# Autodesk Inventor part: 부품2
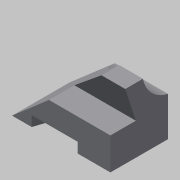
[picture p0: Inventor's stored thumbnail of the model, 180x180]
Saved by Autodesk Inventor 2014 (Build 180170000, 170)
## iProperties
Created: 2015-04
Part Number: 부품2
Material: Generic
Document SubType Name: Modeling
Designer: 203-09
Density: 1 g/cm^3
Appearance: Default
Author: 203-09
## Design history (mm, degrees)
sketch "스케치2"
  geometry: L1 (-43.267, -8)-(-67.621, -8); L2 (-67.621, -8)-(-53, -53); L3 (-53, -53)-(-88, -53); L4 (-88, -53)-(-88, -97); L5 (-88, -97)-(-9, -97); L6 (-9, -97)-(-9, -43.07); A1 r 44 centre (0, 0) between (-43.267, -8) and (-9, -43.07); 1 further point
  constraints: 12 end point, 3 parallel, 2 point on circle, 1 centre point, 1 coincident, 1 horizontal, 1 perpendicular
  dimensions: "d0" = 44 radius of A1; "d1" = 8 distance from line of point (0, 0) L1; "d2" = 9 distance from line of point (0, 0) L6; "d3" = 72 deg angle of L3 L2; "d4" = 44 distance of L3.end L4.end; "d5" = 79 distance of L4.end L5.end; "d6" = 89 distance between parallel lines of L1 L5; "d7" = 35 distance of L2.end L3.end
extrude "돌출1" new body sketch "스케치2" distance "d8" = 135; taper "d9" = 0 deg
sketch "스케치3"
  geometry: L1 (0, -97)-(0, -53) reference; L2 (0, -8)-(-135, -8) reference; L3 (0, -97)-(-102.383, -8); L4 (0, -8)-(0, -97); L5 (0, -8)-(-102.383, -8); L6 (0, -97)-(-135, -97) reference; 1 further point
  constraints: 6 end point, 1 collinear, 1 perpendicular, 1 point on line
  dimensions: "d10" = 139 deg angle of L3 L6
extrude "돌출2" cut sketch "스케치3" stored distance "d11" = 135; taper "d12" = 0 deg
sketch "스케치4"
  geometry: L1 (135, 79)-(0, 79) reference; L2 (135, 0)-(0, 0) reference; L3 (82.331, 79)-(108, 0); L4 (19.244, 79)-(44.912, 0); L5 (82.331, 79)-(19.244, 79); L6 (108, 0)-(44.912, 0); 1 further point
  constraints: 8 end point, 4 point on line, 2 collinear, 1 parallel
  dimensions: "d13" = 27 distance of L3.end L2.start; "d15" = 72 deg angle of L3 L1; "d16" = 60 distance between parallel lines of L4 L3
extrude "돌출3" cut sketch "스케치4" distance "d17" = 14; taper "d18" = 0 deg
node "솔리드1"
